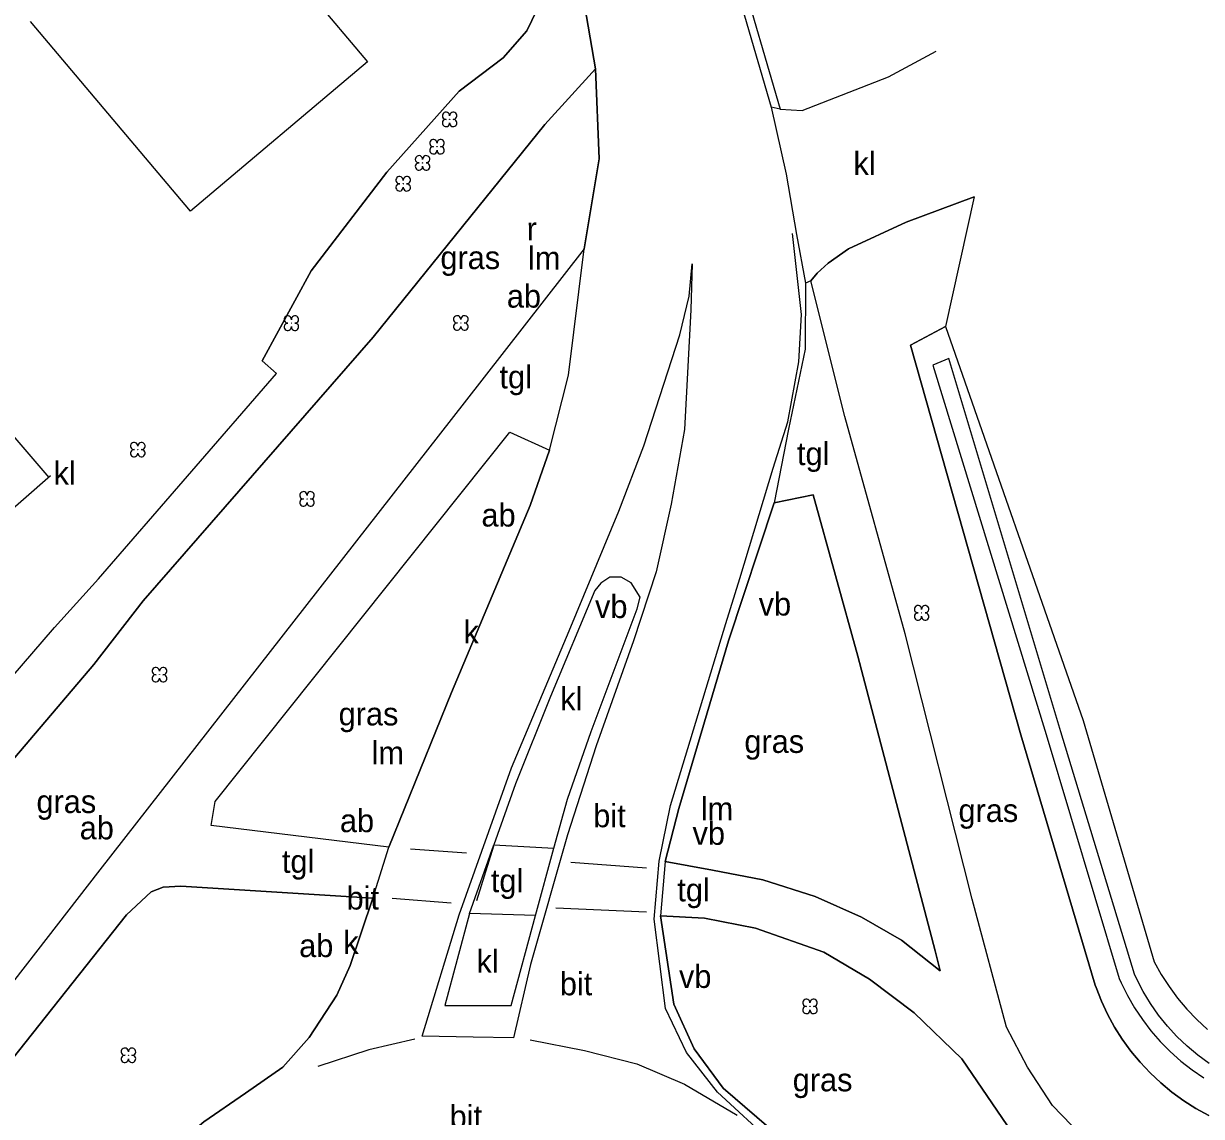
# Model space of a CAD drawing. Extents: x 154825 to 158680, y 370717 to 378075.
# Drawn here: x 156874.8 to 156926, y 372510.6 to 372558.2 of the extents above; entities that cross this region are included whole.
import ezdxf

# ---------------------------------------------------------------- set-up
doc = ezdxf.new("R2010")
doc.units = 0
for name, color, linetype in [('ab zonder kabel', 7, 'Continuous'), ('bitumenverharding(vs)', 7, 'Continuous'), ('boom', 7, 'Continuous'), ('breuklijn', 7, 'Continuous'), ('deelstreep', 7, 'Continuous'), ('deelstreep(1-1)', 7, 'Continuous'), ('driehoekmarkering', 7, 'Continuous'), ('grazige vegetatie(vs)', 7, 'Continuous'), ('haag geschoren', 7, 'Continuous'), ('insteek sloot', 7, 'Continuous'), ('kantstreep', 7, 'Continuous'), ('klinkerverharding(vs)', 7, 'Continuous'), ('kolk', 7, 'Continuous'), ('maaiveldlijn algemeen - gesloten verharding', 7, 'Continuous'), ('maaiveldlijn algemeen - muur', 7, 'Continuous'), ('maaiveldlijn algemeen - verharding algemeen', 7, 'Continuous'), ('raster - hek', 7, 'Continuous'), ('rioolput(z_inl)', 7, 'Continuous'), ('Sloot bodem', 7, 'Continuous'), ('tegelverh(vs)', 7, 'Continuous'), ('verkeersb_z kabel', 7, 'Continuous'), ('verlichtingsobject', 7, 'Continuous'), ('vlak_Grazige_vegetatie', 7, 'Continuous')]:
    doc.layers.add(name, color=color, linetype=linetype)

msp = doc.modelspace()

# ---------------------------------------------------------------- linework, layer by layer
at = {"layer": 'boom'}
for centre in [(156893.31, 372554.006), (156892.763, 372552.816), (156892.134, 372552.114), (156891.291, 372551.204), (156886.425, 372545.139), (156893.8, 372545.149), (156879.74, 372539.635), (156887.105, 372537.491), (156913.854, 372532.532), (156880.684, 372529.84), (156908.996, 372515.406), (156879.333, 372513.279)]:
    msp.add_circle(centre, 0.006, dxfattribs=at)
for centre, start, end in [((156893.152, 372554.164), 357.075, 272.925), ((156893.468, 372554.164), 267.075, 182.925), ((156893.152, 372553.848), 87.075, 2.925), ((156893.468, 372553.848), 177.075, 92.925), ((156892.605, 372552.974), 357.075, 272.925), ((156892.605, 372552.658), 87.075, 2.925), ((156892.921, 372552.974), 267.075, 182.925), ((156892.921, 372552.658), 177.075, 92.925), ((156891.975, 372552.272), 357.075, 272.925), ((156892.292, 372552.272), 267.075, 182.925), ((156891.975, 372551.956), 87.075, 2.925), ((156892.292, 372551.956), 177.075, 92.925), ((156891.133, 372551.362), 357.075, 272.925), ((156891.133, 372551.046), 87.075, 2.925), ((156891.449, 372551.362), 267.075, 182.925), ((156891.449, 372551.046), 177.075, 92.925), ((156886.267, 372545.297), 357.075, 272.925), ((156886.267, 372544.981), 87.075, 2.925), ((156886.583, 372545.297), 267.075, 182.925), ((156886.583, 372544.981), 177.075, 92.925), ((156893.642, 372545.307), 357.075, 272.925), ((156893.642, 372544.99), 87.075, 2.925), ((156893.958, 372545.307), 267.075, 182.925), ((156893.958, 372544.99), 177.075, 92.925), ((156879.582, 372539.793), 357.075, 272.925), ((156879.898, 372539.793), 267.075, 182.925), ((156879.582, 372539.477), 87.075, 2.925), ((156879.898, 372539.477), 177.075, 92.925), ((156886.947, 372537.649), 357.075, 272.925), ((156886.947, 372537.333), 87.075, 2.925), ((156887.263, 372537.649), 267.075, 182.925), ((156887.263, 372537.333), 177.075, 92.925), ((156913.696, 372532.69), 357.075, 272.925), ((156914.012, 372532.69), 267.075, 182.925), ((156913.696, 372532.374), 87.075, 2.925), ((156914.012, 372532.374), 177.075, 92.925), ((156880.526, 372529.998), 357.075, 272.925), ((156880.842, 372529.998), 267.075, 182.925), ((156880.526, 372529.682), 87.075, 2.925), ((156880.842, 372529.682), 177.075, 92.925), ((156908.838, 372515.564), 357.075, 272.925), ((156908.838, 372515.248), 87.075, 2.925), ((156909.154, 372515.564), 267.075, 182.925), ((156909.154, 372515.248), 177.075, 92.925), ((156879.175, 372513.437), 357.075, 272.925), ((156879.175, 372513.121), 87.075, 2.925), ((156879.491, 372513.437), 267.075, 182.925), ((156879.491, 372513.121), 177.075, 92.925)]:
    msp.add_arc(centre, 0.158, start, end, dxfattribs=at)
at = {"layer": 'breuklijn'}
msp.add_lwpolyline([(156846.549, 372494.899), (156849.905, 372497.933), (156856.513, 372505.993), (156862.994, 372514.234), (156871.098, 372522.372), (156877.833, 372530.284), (156879.967, 372533.054), (156889.984, 372544.53), (156897.461, 372553.778), (156899.668, 372556.213)], dxfattribs=at)
at = {"layer": 'deelstreep'}
for points in [[(156894.05, 372522.071), (156891.605, 372522.243)], [(156898.581, 372521.688), (156901.879, 372521.441)], [(156890.811, 372520.118), (156893.381, 372519.908)], [(156901.879, 372519.511), (156897.932, 372519.676)]]:
    msp.add_lwpolyline(points, dxfattribs=at)
at = {"layer": 'deelstreep(1-1)'}
for points in [[(156907.4, 372538.829), (156908.039, 372540.85), (156908.511, 372543.459), (156908.63, 372545.512), (156908.24, 372549.045)], [(156896.811, 372513.948), (156899.175, 372513.487), (156901.455, 372512.901), (156903.539, 372512.027), (156905.829, 372510.675)]]:
    msp.add_lwpolyline(points, dxfattribs=at)
at = {"layer": 'driehoekmarkering'}
for points in [[(156894.49, 372520.015), (156895.242, 372522.399)], [(156891.799, 372513.984), (156889.801, 372513.509), (156887.578, 372512.788)]]:
    msp.add_lwpolyline(points, dxfattribs=at)
at = {"layer": 'haag geschoren'}
msp.add_lwpolyline([(156897.534, 372561.86), (156897.596, 372560.638), (156897.323, 372559.218), (156896.677, 372557.867), (156895.641, 372556.685), (156893.725, 372555.229), (156890.585, 372551.703), (156887.282, 372547.412), (156885.152, 372543.495)], dxfattribs=at)
at = {"layer": 'insteek sloot'}
msp.add_lwpolyline([(156926.351, 372510.656), (156925.796, 372510.961), (156925.261, 372511.301), (156924.748, 372511.673), (156924.26, 372512.077), (156923.798, 372512.511), (156923.364, 372512.973), (156922.961, 372513.461), (156922.589, 372513.974), (156922.25, 372514.509), (156921.946, 372515.064), (156921.677, 372515.638), (156921.445, 372516.227), (156921.41, 372516.325), (156918.175, 372527.22), (156913.37, 372544.182), (156914.889, 372544.996), (156920.893, 372527.849), (156923.974, 372517.345), (156924.282, 372516.798), (156924.624, 372516.272), (156924.998, 372515.768), (156925.404, 372515.287), (156925.839, 372514.833), (156926.302, 372514.407)], dxfattribs=at)
at = {"layer": 'kantstreep'}
for points in [[(156899.683, 372526.743), (156898.447, 372522.871), (156896.834, 372517.224), (156896.098, 372514.036), (156894.331, 372514.067), (156892.113, 372514.109), (156893.731, 372519.393), (156895.998, 372525.785), (156898.512, 372531.743), (156900.679, 372536.951), (156901.76, 372539.802), (156903.333, 372544.626), (156903.733, 372546.311), (156903.865, 372547.714), (156903.81, 372545.716), (156903.54, 372540.504), (156902.952, 372537.262), (156902.298, 372534.322), (156901.309, 372531.312), (156899.683, 372526.743)], [(156931.037, 372501.272), (156922.497, 372500.81), (156920.255, 372500.797), (156919.456, 372500.822), (156916.878, 372501.313), (156915.128, 372501.939), (156913.941, 372502.684), (156912.214, 372504.127), (156910.776, 372505.761), (156909.216, 372507.621), (156907.396, 372509.44), (156904.973, 372511.675), (156903.618, 372513.394), (156902.711, 372515.314), (156902.211, 372519.202), (156902.433, 372521.732), (156902.919, 372524.148), (156905.331, 372532.066), (156905.937, 372534.024), (156907.4, 372538.829)]]:
    msp.add_lwpolyline(points, dxfattribs=at)
at = {"layer": 'maaiveldlijn algemeen - gesloten verharding'}
for points in [[(156894.338, 372578.885), (156900.547, 372570.698), (156902.664, 372567.533), (156904.055, 372564.538), (156905.564, 372560.519), (156907.313, 372554.538)], [(156899.668, 372556.213), (156898.878, 372560.774), (156898.167, 372564.475), (156897.163, 372566.938)], [(156899.173, 372548.379), (156899.825, 372552.294), (156899.668, 372556.213)], [(156907.313, 372554.538), (156907.953, 372551.624), (156908.406, 372549.004), (156908.799, 372546.873)], [(156897.657, 372539.607), (156898.487, 372542.873), (156899.173, 372548.379)], [(156908.799, 372546.873), (156908.788, 372544.012), (156908.056, 372540.525), (156907.434, 372537.32)], [(156890.662, 372522.331), (156893.397, 372529.07), (156896.811, 372537.201), (156897.657, 372539.607)], [(156907.434, 372537.32), (156905.446, 372531.315), (156903.282, 372524.02), (156902.692, 372521.705)], [(156897.847, 372522.288), (156898.445, 372524.429), (156899.473, 372527.362), (156901.474, 372532.701), (156901.605, 372533.221), (156901.207, 372533.842), (156900.781, 372534.081), (156900.283, 372534.092), (156899.896, 372533.818), (156899.632, 372533.51), (156897.708, 372528.888), (156896.184, 372525.085), (156895.231, 372522.43)], [(156889.965, 372520.122), (156890.662, 372522.331)], [(156894.173, 372519.449), (156895.231, 372522.43)], [(156895.235, 372522.44), (156895.231, 372522.43)], [(156897.05, 372519.368), (156897.847, 372522.288)], [(156902.692, 372521.705), (156902.491, 372519.341)], [(156868.148, 372495.483), (156870.212, 372496.312), (156872.281, 372497.541), (156873.82, 372498.894), (156875.205, 372500.42), (156875.953, 372501.678), (156877.151, 372503.946), (156878.25, 372505.823), (156879.449, 372507.359), (156880.966, 372508.985), (156882.621, 372510.382), (156884.434, 372511.634), (156886.05, 372512.766), (156887.195, 372514.05), (156888.402, 372515.9), (156888.98, 372517.192), (156889.965, 372520.122)], [(156894.173, 372519.449), (156893.102, 372515.443), (156895.992, 372515.439), (156897.05, 372519.368)], [(156902.491, 372519.341), (156903.07, 372515.508), (156903.952, 372513.558), (156905.22, 372511.854), (156907.627, 372509.771), (156909.428, 372507.92), (156911.03, 372506.034), (156912.555, 372504.366), (156914.197, 372503.064), (156915.343, 372502.357), (156916.938, 372501.668), (156919.423, 372501.17), (156920.418, 372501.065)]]:
    msp.add_lwpolyline(points, dxfattribs=at)
at = {"layer": 'maaiveldlijn algemeen - muur'}
for points in [[(156882.378, 372565.224), (156889.736, 372556.505), (156882.035, 372550.006), (156875.066, 372558.264)], [(156875.934, 372538.489), (156866.16, 372529.936), (156859.434, 372537.622), (156869.208, 372546.175), (156875.865, 372538.428)]]:
    msp.add_lwpolyline(points, dxfattribs=at)
at = {"layer": 'maaiveldlijn algemeen - verharding algemeen'}
for points in [[(156894.338, 372578.885), (156894.506, 372579.336), (156900.817, 372570.933), (156902.944, 372567.745), (156904.469, 372564.67), (156905.891, 372560.672), (156907.697, 372554.456)], [(156907.697, 372554.456), (156908.649, 372554.4), (156912.42, 372555.856), (156914.49, 372556.978)], [(156907.697, 372554.456), (156907.313, 372554.538)], [(156916.137, 372550.634), (156913.178, 372549.534), (156910.673, 372548.372), (156909.786, 372547.75), (156909.313, 372547.319), (156909.032, 372546.974)], [(156899.173, 372548.379), (156893.944, 372541.673), (156878.09, 372521.354), (156871.567, 372512.962), (156866.271, 372506.339), (156865.149, 372504.579), (156864.759, 372503.351), (156864.546, 372502.256), (156864.61, 372501.094), (156864.796, 372499.727), (156866.184, 372494.747)], [(156909.032, 372546.974), (156908.799, 372546.873)], [(157014.85, 372524.672), (157010.079, 372522.89), (157000.91, 372519.957), (156990.65, 372516.891), (156975.11, 372512.379), (156967.848, 372510.911), (156955.026, 372508.717), (156934.53, 372506.867), (156929.026, 372506.699), (156925.826, 372507.192), (156923.561, 372507.931), (156921.201, 372509.389), (156919.545, 372511.1), (156918.463, 372512.757), (156917.555, 372514.506), (156916.059, 372520.074), (156913.132, 372531.614), (156910.506, 372541.082), (156909.032, 372546.974)], [(156890.662, 372522.331), (156882.935, 372523.28), (156883.109, 372524.32), (156895.938, 372540.388), (156897.657, 372539.607)], [(156902.692, 372521.705), (156904.747, 372521.329), (156906.945, 372520.91), (156909.222, 372520.184), (156911.236, 372519.288), (156912.974, 372518.288), (156914.659, 372516.961), (156914.44, 372517.822), (156911.084, 372530.649), (156909.135, 372537.661), (156907.434, 372537.32)], [(156895.235, 372522.44), (156897.847, 372522.288)], [(156889.965, 372520.122), (156881.608, 372520.637), (156880.841, 372520.593), (156880.328, 372520.392), (156879.248, 372519.393), (156873.102, 372511.642), (156867.969, 372505.126), (156867.261, 372504.105), (156866.831, 372503.169), (156866.636, 372502.044), (156866.636, 372501.116), (156866.896, 372500.065), (156868.148, 372495.483)], [(156897.05, 372519.368), (156894.173, 372519.449)], [(156920.418, 372501.065), (156920.269, 372501.343), (156920.185, 372503.385), (156919.708, 372505.678), (156918.517, 372508.392), (156917.597, 372510.202), (156915.611, 372513.124), (156913.529, 372515.119), (156911.591, 372516.595), (156909.592, 372517.762), (156906.62, 372518.808), (156904.399, 372519.251), (156902.491, 372519.341)]]:
    msp.add_lwpolyline(points, dxfattribs=at)
at = {"layer": 'raster - hek'}
msp.add_lwpolyline([(156845.629, 372503.985), (156848.71, 372500.143), (156854.823, 372507.239), (156862.068, 372515.653), (156869.178, 372523.863), (156876.112, 372531.891), (156878.026, 372534.012), (156885.775, 372542.945), (156885.152, 372543.495)], dxfattribs=at)
at = {"layer": 'Sloot bodem'}
msp.add_lwpolyline([(156926.377, 372512.918), (156925.883, 372513.28), (156925.413, 372513.674), (156924.97, 372514.098), (156924.555, 372514.55), (156924.171, 372515.028), (156923.819, 372515.529), (156923.5, 372516.053), (156923.216, 372516.596), (156923.119, 372516.803), (156919.913, 372527.353), (156915.046, 372543.594), (156914.34, 372543.306), (156919.269, 372527.245), (156922.459, 372516.62), (156922.541, 372516.435), (156922.813, 372515.881), (156923.121, 372515.346), (156923.463, 372514.832), (156923.838, 372514.341), (156924.243, 372513.875), (156924.678, 372513.437), (156925.14, 372513.027), (156925.628, 372512.649), (156926.139, 372512.302)], dxfattribs=at)
at = {"layer": 'vlak_Grazige_vegetatie'}
for points in [[(156898.878, 372560.774), (156899.668, 372556.213), (156897.461, 372553.778), (156889.984, 372544.53), (156879.967, 372533.054), (156877.833, 372530.284), (156871.098, 372522.372)], [(156869.178, 372523.863), (156876.112, 372531.891), (156878.026, 372534.012), (156885.775, 372542.945), (156885.152, 372543.495), (156887.282, 372547.412), (156890.585, 372551.703), (156893.725, 372555.229), (156895.641, 372556.685), (156896.677, 372557.867), (156897.323, 372559.218)], [(156871.098, 372522.372), (156877.833, 372530.284), (156879.967, 372533.054), (156889.984, 372544.53), (156897.461, 372553.778), (156899.668, 372556.213), (156899.825, 372552.294), (156899.173, 372548.379), (156893.944, 372541.673), (156878.09, 372521.354), (156871.567, 372512.962)], [(156921.201, 372509.389), (156919.545, 372511.1), (156918.463, 372512.757), (156917.556, 372514.505), (156916.059, 372520.074), (156913.132, 372531.614), (156910.506, 372541.082), (156909.032, 372546.974), (156909.313, 372547.319), (156909.786, 372547.75), (156910.673, 372548.372), (156913.178, 372549.534), (156916.137, 372550.634), (156914.889, 372544.996), (156913.37, 372544.182), (156918.175, 372527.22), (156921.41, 372516.325), (156921.445, 372516.227), (156921.677, 372515.638), (156921.946, 372515.064), (156922.25, 372514.509), (156922.589, 372513.974), (156922.961, 372513.461), (156923.364, 372512.973), (156923.798, 372512.511), (156924.26, 372512.077), (156924.748, 372511.673), (156925.261, 372511.301), (156925.796, 372510.961), (156926.351, 372510.656)], [(156926.351, 372510.656), (156925.796, 372510.961), (156925.261, 372511.301), (156924.748, 372511.673), (156924.26, 372512.077), (156923.798, 372512.511), (156923.364, 372512.973), (156922.961, 372513.461), (156922.589, 372513.974), (156922.25, 372514.509), (156921.946, 372515.064), (156921.677, 372515.638), (156921.445, 372516.227), (156921.41, 372516.325), (156918.175, 372527.22), (156913.37, 372544.182), (156914.889, 372544.996), (156920.893, 372527.848), (156923.974, 372517.345), (156924.282, 372516.799), (156924.624, 372516.272), (156924.998, 372515.768), (156925.404, 372515.288), (156925.839, 372514.833), (156926.302, 372514.407)], [(156926.377, 372512.918), (156925.883, 372513.28), (156925.413, 372513.674), (156924.97, 372514.098), (156924.555, 372514.55), (156924.171, 372515.028), (156923.819, 372515.529), (156923.5, 372516.053), (156923.216, 372516.596), (156923.119, 372516.803), (156919.913, 372527.353), (156915.046, 372543.594), (156914.34, 372543.306), (156919.269, 372527.245), (156922.459, 372516.62), (156922.541, 372516.435), (156922.813, 372515.881), (156923.121, 372515.346), (156923.463, 372514.832), (156923.838, 372514.341), (156924.243, 372513.875), (156924.678, 372513.437), (156925.14, 372513.027), (156925.628, 372512.649), (156926.139, 372512.302)], [(156873.102, 372511.642), (156879.248, 372519.393), (156880.328, 372520.392), (156880.841, 372520.593), (156881.608, 372520.637), (156889.965, 372520.122), (156888.98, 372517.192), (156888.402, 372515.9), (156887.194, 372514.05), (156886.05, 372512.766), (156884.434, 372511.634), (156882.621, 372510.382), (156880.966, 372508.985), (156879.449, 372507.359), (156878.25, 372505.823), (156877.151, 372503.946), (156875.953, 372501.678), (156875.205, 372500.42), (156873.82, 372498.894)]]:
    msp.add_lwpolyline(points, dxfattribs=at)
for points in [[(156893.397, 372529.07), (156890.662, 372522.331), (156882.935, 372523.28), (156883.109, 372524.32), (156895.938, 372540.388), (156897.657, 372539.606), (156896.811, 372537.201)], [(156914.44, 372517.822), (156914.659, 372516.961), (156912.974, 372518.288), (156911.236, 372519.288), (156909.222, 372520.184), (156906.945, 372520.91), (156904.747, 372521.329), (156902.692, 372521.705), (156903.282, 372524.02), (156905.446, 372531.315), (156907.434, 372537.32), (156909.135, 372537.661), (156911.084, 372530.649)], [(156920.269, 372501.343), (156920.418, 372501.065), (156919.423, 372501.17), (156916.938, 372501.668), (156915.343, 372502.357), (156914.197, 372503.064), (156912.555, 372504.365), (156911.03, 372506.034), (156909.428, 372507.92), (156907.627, 372509.771), (156905.22, 372511.854), (156903.952, 372513.558), (156903.07, 372515.508), (156902.491, 372519.341), (156904.399, 372519.251), (156906.62, 372518.808), (156909.592, 372517.762), (156911.591, 372516.595), (156913.529, 372515.119), (156915.611, 372513.124), (156917.597, 372510.202), (156918.517, 372508.392), (156919.708, 372505.678), (156920.185, 372503.385)]]:
    msp.add_lwpolyline(points, close=True, dxfattribs=at)

# ---------------------------------------------------------------- texts
at = {"layer": 'ab zonder kabel'}
for p in [(156895.802, 372545.816), (156894.697, 372536.289), (156888.537, 372522.989), (156877.211, 372522.676), (156886.763, 372517.552)]:
    msp.add_text('ab', height=1, dxfattribs=at).set_placement(p)
at = {"layer": 'bitumenverharding(vs)'}
for p in [(156899.563, 372523.204), (156888.826, 372519.622), (156898.109, 372515.89), (156893.312, 372510.108)]:
    msp.add_text('bit', height=1, dxfattribs=at).set_placement(p)
at = {"layer": 'grazige vegetatie(vs)'}
for p in [(156892.911, 372547.492), (156888.481, 372527.634), (156906.141, 372526.438), (156875.329, 372523.821), (156915.459, 372523.432), (156908.245, 372511.711)]:
    msp.add_text('gras', height=1, dxfattribs=at).set_placement(p)
at = {"layer": 'klinkerverharding(vs)'}
for p in [(156910.887, 372551.593), (156876.074, 372538.111), (156898.125, 372528.289), (156894.479, 372516.87)]:
    msp.add_text('kl', height=1, dxfattribs=at).set_placement(p)
at = {"layer": 'kolk'}
for p in [(156893.913, 372531.201), (156888.686, 372517.688)]:
    msp.add_text('k', height=1, dxfattribs=at).set_placement(p)
at = {"layer": 'rioolput(z_inl)'}
msp.add_text('r', height=1, dxfattribs=at).set_placement((156896.667, 372548.746))
at = {"layer": 'tegelverh(vs)'}
for p in [(156895.482, 372542.299), (156908.43, 372538.961), (156886.011, 372521.219), (156895.106, 372520.377), (156903.221, 372519.976)]:
    msp.add_text('tgl', height=1, dxfattribs=at).set_placement(p)
at = {"layer": 'verkeersb_z kabel'}
for p in [(156899.642, 372532.309), (156906.764, 372532.416), (156903.885, 372522.439), (156903.295, 372516.211)]:
    msp.add_text('vb', height=1, dxfattribs=at).set_placement(p)
at = {"layer": 'verlichtingsobject'}
for p in [(156896.724, 372547.473), (156889.914, 372525.941), (156904.243, 372523.51)]:
    msp.add_text('lm', height=1, dxfattribs=at).set_placement(p)

doc.saveas('drawing.dxf')
